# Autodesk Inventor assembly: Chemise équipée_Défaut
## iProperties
Shininess: 64.0
Length Units: 11269
Angle Units: 11279
Time Units: 11290
Mass Units: 11283
Length Display Precision: 3
Angle Display Precision: 2
Compacted: True
Created: 2006-01
Part Number: Chemise équipée_Défaut
Document SubType Name: Assembly
Designer: riri
Density: 0.0
Volumn: 0.0
Area: 0.0
PropertySet Name: Model Information
Control State: 0
Master: False
Checked Out: False
Author: riri
